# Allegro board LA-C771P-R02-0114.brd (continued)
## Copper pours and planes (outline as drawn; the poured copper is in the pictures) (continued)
BOOT1 on BOTTOM (solid shape): 153.17,63.64 154.22,63.64 154.3,63.57 154.3,63.39 154.23,63.33 152.5,63.33 151.84,63.99 150.8,63.99 150.68,64.11 150.68,64.73 150.78,64.83 151.98,64.83
BOOTG on BOTTOM (solid shape): 160.15,65.01 160.25,65.01 160.33,64.93 160.33,64.02 160.23,63.92 159.9,63.92 159.84,63.86 158.93,62.95 157.48,62.95 157.42,63.01 157.42,63.14 157.48,63.2 158.32,63.2 158.33,63.2 159.26,64.13 159.26,64.67 159.67,65.09 160.08,65.09
BQ24780VDD on BOTTOM (solid shape): 198.78,70.65 198.78,70.52 198.72,70.47 197.91,70.47 197.86,70.42 197.71,70.42 197.4,70.11 197.12,70.11 197.02,70.21 197.02,70.52 197.11,70.61 197.14,70.6 197.27,70.6 197.39,70.65 197.81,70.65 197.84,70.65 197.89,70.7 198.72,70.7
BST_3V on BOTTOM (solid shape): 189.42,40.57 189.92,40.57 189.92,40.57 190,40.57 190.12,40.45 190.12,39.94 190.07,39.89 189.47,39.89 189.36,40 188.85,40 188.79,40.06 187.94,40.06 187.92,40.09 187.92,40.85 188.02,40.95 189.04,40.95
BST_5V on BOTTOM (solid shape): 48.37,48.92 48.37,48.22 48.31,48.16 48.24,48.16 48.23,48.14 47.53,48.14 47.47,48.08 46.12,48.08 46.05,48.16 46.05,48.72 46.14,48.8 47.05,48.8 47.29,49.05 48.24,49.05
BST_CHG on BOTTOM (solid shape): 196.55,71.08 198.72,71.08 198.78,71.03 198.78,70.93 198.72,70.87 197.86,70.87 197.76,70.77 196.97,70.77 196.5,70.3 195.8,70.3 195.8,71.19 196.44,71.19
BST_DDR on BOTTOM (solid shape): 150.05,32.02 150.05,32.01 150.5,31.57 151.72,31.57 152.53,31.57 152.57,31.53 152.57,31.39 152.53,31.35 151.7,31.35 151.64,31.29 150.41,31.29 150.24,31.12 150.24,30.68 150.18,30.61 149.35,30.61 149.29,30.68 149.29,32.21 149.42,32.33 149.73,32.33
BST_DDR_R on BOTTOM (solid shape): 150.31,29.85 150.31,26.82 150.15,26.66 149.31,26.66 149.2,26.77 149.2,28.34 149.29,28.43 149.29,29.85 149.35,29.92 150.24,29.92
CPU_B+ on TOP (solid shape): 157.23,83.45 157.23,82.93 157.45,82.71 158.79,82.71 159.37,82.12 163.56,82.12 163.58,82.1 163.81,82.1 165.08,80.83 165.08,79.51 166.15,78.44 166.15,75.19 165.51,74.56 162.01,74.56 161.48,74.02 161.48,72.81 161.2,72.53 158.23,72.53 158.13,72.63 158.13,73.3 157.94,73.49 157.12,73.49 157.12,73.48 156.22,73.48 156.06,73.65 156.06,74.36 155.87,74.55 155.36,74.55 155.28,74.63 155.28,75.14 155.37,75.23 158.07,75.23 158.36,75.52 158.36,78.35 158.36,78.4 158.36,78.45 158.36,78.97 158.37,79.04 158.36,79.12 158.36,81.8 158.06,82.1 155.37,82.1 155.25,82.22 155.25,83.44 155.39,83.59 157.09,83.59
CPU_B+ on BOTTOM (solid shape): 165.11,80.65 165.11,75.37 164.35,74.61 162.11,74.61 161.53,74.02 161.53,72.86 161.2,72.53 158.22,72.53 158.15,72.6 158.15,76.64 158.42,76.91 158.42,79.48 158.45,79.51 158.45,81.46 159.01,82.03 163.4,82.03 163.48,82.1 163.66,82.1
DCHG_I on TOP (solid shape): 203.36,73.35 203.36,72.4 203.23,72.27 202.6,72.27 202.34,72.53 202.34,73.48 203.23,73.48
DH_CHG on TOP (solid shape): 194.22,72.22 194.22,71.19 194.09,71.07 193.2,71.07 193.07,71.19 193.07,72.27 193.2,72.4 194.04,72.4
DH_CHG on BOTTOM (solid shape): 197.66,71.54 197.89,71.53 197.94,71.48 198.72,71.48 198.78,71.43 198.78,71.33 198.72,71.28 197.89,71.28 197.81,71.21 197.39,71.21 197.21,71.26 197.04,71.21 196.67,71.21 196.59,71.28 196.59,71.57 196.73,71.71 197.48,71.71
DH_CHG on IN2 (solid shape): 197.65,71.57 197.65,70.94 197.52,70.81 196.12,70.81 195.99,70.68 193.2,70.68 193.07,70.81 193.07,71.57 193.2,71.7 197.52,71.7
DL_CHG on TOP (solid shape): 192.11,66.84 192.11,65.77 191.93,65.59 190.96,65.59 190.84,65.72 190.84,66.76 191.09,67.01 191.93,67.01
DL_CHG on BOTTOM (solid shape): 198.78,70.24 198.78,70.11 198.72,70.06 197.94,70.06 197.68,69.81 197.68,69.58 197.56,69.45 196.63,69.45 196.46,69.62 196.46,69.88 196.57,69.99 197.48,69.99 197.78,70.29 198.72,70.29
DL_CHG on IN2 (solid shape): 194.04,66.46 194.04,65.95 193.63,65.54 191.52,65.54 191.35,65.72 191.35,66.63 191.55,66.84 193.66,66.84
DL_CHG on IN2 (solid shape): 197.52,69.86 197.52,69.44 197.43,69.35 197.12,69.35 196.49,68.72 195.8,68.72 195.74,68.78 195.74,69.36 196.36,69.99 197.39,69.99
ECAGND on TOP (solid shape): 68.74,10.4 68.74,7.22 68.18,6.66 67.43,6.66 67.16,6.94 67.13,6.96 67.07,7.01 67,7.05 66.93,7.08 66.86,7.1 66.86,7.34 66.89,7.37 66.89,8.26 66.89,8.29 66.89,8.34 66.88,8.37 66.88,8.54 67.62,8.54 67.62,8.49 67.63,8.44 67.65,8.39 67.67,8.34 67.7,8.3 67.74,8.26 67.78,8.22 67.82,8.2 67.87,8.18 67.92,8.17 67.98,8.16 68.03,8.17 68.08,8.18 68.13,8.2 68.18,8.22 68.22,8.26 68.26,8.3 68.29,8.34 68.31,8.39 68.33,8.44 68.33,8.49 68.33,8.54 68.33,8.6 68.31,8.65 68.29,8.7 68.26,8.74 68.22,8.78 68.18,8.81 68.13,8.84 68.08,8.86 68.03,8.87 67.98,8.87 67.92,8.87 67.87,8.86 67.82,8.84 67.78,8.81 67.74,8.78 67.7,8.74 67.67,8.7 67.65,8.65 67.63,8.6 67.62,8.54 66.88,8.54 66.88,9.15 66.88,9.19 66.87,9.27 66.86,9.31 66.86,9.38 66.88,9.4 66.91,9.42 66.97,9.46 66.99,9.48 67.36,9.85 67.36,9.9 67.39,9.94 67.39,10.85 67.44,10.91 68.23,10.91
EXT_MIC_RING2 on TOP (solid shape): 20.86,26.68 20.86,26.36 20.8,26.27 20.69,26.29 20.11,26.2 20.4,25.69 20.48,25.62 20.46,25.52 20.23,25.28 19.08,25.28 18.96,25.41 18.96,27.31 19.08,27.44 20.1,27.44
EXT_MIC_SLEEVE on TOP (solid shape): 20.78,25.26 20.94,25.11 20.94,24.9 20.8,24.77 20.78,24.77 20.57,24.74 20.42,24.59 20.25,24.42 20.25,23.71 19.69,23.15 19.03,23.15 18.96,23.22 18.96,24.98 19.13,25.15 20.35,25.15 20.48,25.28 20.78,25.28
HGNDB on TOP (solid shape): 16.52,16.42 16.52,15.88 16.4,15.77 16.4,14.58 16.39,14.56 16.39,13.7 16.21,13.52 14.94,13.52 14.79,13.67 14.79,15.02 15.32,15.55 15.32,16.47 15.5,16.65 16.29,16.65
HGNDB on IN2 (solid shape): outline of 159 points within 1.27,12.72 16.31,18.55
LANGND on TOP (solid shape): 18.32,73.38 18.32,72.73 18.17,72.57 16.75,72.57 16.44,72.88 16.44,73.97 16.61,74.14 17.56,74.14
LANGND on TOP (solid shape): outline of 107 points within 5.72,60.29 20.2,63.56
LANGND on BOTTOM (solid shape): 8.79,78.42 15.12,78.42 15.16,78.38 17.04,78.38 18,77.42 18,73.6 17.69,73.28 16.03,73.28 15.58,73.74 15.58,74.22 12.22,77.58 10.44,77.58 10.38,77.63 10.31,77.67 9.09,77.67 8.97,77.55 6.41,77.55 6.1,77.86 6.1,78.44 6.41,78.75 8.47,78.75
LANGND on IN1 (solid shape): outline of 205 points within 6.15,60.23 18.57,78.82
LG_DDR on TOP (solid shape): 148.46,28.97 148.46,28.04 148.32,27.89 147.43,27.89 147.33,28 147.33,28.91 147.45,29.04 148.39,29.04
LG_DDR on BOTTOM (solid shape): 152.97,30.3 152.97,29.53 152.59,29.15 152.59,28.96 152.5,28.87 152.18,28.87 152.02,29.03 152.02,29.79 152.31,30.07 152.62,30.07 152.7,30.14 152.7,30.27 152.77,30.35 152.92,30.35
LG_DDR on IN2 (solid shape): 152.59,29.85 152.59,28.81 152.26,28.48 152.26,28.25 151.77,27.76 148.15,27.76 147.96,27.95 147.96,27.95 147.89,28.02 147.89,28.86 147.99,28.96 148.37,28.96 148.82,28.52 151.09,28.52 151.94,29.37 151.96,29.37 151.96,29.85 152.08,29.98 152.47,29.98
LGATE1 on TOP (solid shape): 155.92,77.55 155.92,76.74 155.82,76.64 155.54,76.64 155.27,76.91 154.84,76.91 154.78,76.97 154.78,77.77 154.84,77.83 155.65,77.83
LGATE1 on BOTTOM (solid shape): 155.68,65.74 155.68,64.95 155.41,64.68 155.41,63.69 155.36,63.64 155.17,63.64 155.13,63.68 155.13,65.17 155.13,65.81 155.23,65.91 155.51,65.91
LGATE1 on IN2 (solid shape): 155.9,66.28 155.9,65.05 155.57,64.72 155.23,64.72 155.13,64.83 155.13,66.35 155.18,66.4 155.78,66.4
LGATE1 on IN2 (solid shape): 156.34,77.2 156.34,76.67 156.22,76.54 155.86,76.54 155.68,76.72 155.14,76.72 154.76,77.1 154.76,77.61 154.99,77.84 155.71,77.84
LGATEG on TOP (solid shape): 158.23,80.54 158.23,79.52 158.14,79.43 157.22,79.43 157.1,79.56 157.1,79.84 157.36,80.09 157.36,80.51 157.49,80.64 158.13,80.64
LGATEG on BOTTOM (solid shape): 157.66,65.89 157.66,65.31 156.99,64.64 156.99,63.67 156.91,63.59 156.81,63.59 156.73,63.67 156.73,65.23 156.79,65.41 156.73,65.6 156.73,65.78 156.9,65.95 157.59,65.95
LGATEG on IN2 (solid shape): 157.77,66.11 157.77,65.46 157.12,64.81 156.88,64.81 156.74,64.94 156.74,66.29 156.84,66.38 157.5,66.38
LGATEG on IN2 (solid shape): 158.99,80.6 158.99,79.74 158.81,79.57 158.09,79.57 157.95,79.43 157.2,79.43 157.1,79.52 157.1,80.5 157.31,80.71 158.88,80.71
LINE2-L on TOP (solid shape): 22.18,22.34 22.18,22.1 21.85,21.77 21.04,20.96 20.33,20.96 19.72,20.35 19.26,20.35 19.08,20.53 19.08,21.88 19.18,21.98 19.91,21.98 20.17,21.72 20.84,21.72 21.28,22.16 21.28,22.32 21.33,22.38 22.14,22.38
LINE2-MIC on TOP (solid shape): 18.93,21.09 18.93,19.9 18.75,19.72 17.76,19.72 17.58,19.9 17.58,21.09 17.71,21.22 18.8,21.22
LINE2-MIC on TOP (solid shape): 25.33,19.01 25.33,18.27 25.33,18.26 25.33,17.91 25.18,17.76 24.87,17.76 24.72,17.92 24.6,17.92 24.49,17.98 24.38,18.03 23.73,18.68 23.73,18.83 24.26,19.36 24.98,19.36
LINE2-MIC on BOTTOM (solid shape): 25.56,77.33 25.56,76.03 25.41,75.88 20.56,75.88 20.23,76.21 20.23,77.22 20.63,77.63 25.26,77.63
LINE2-MIC on IN1 (solid shape): 27.24,77.12 27.24,76.11 27.02,75.89 24.71,75.89 24.37,76.23 24.37,77.02 24.68,77.34 27.02,77.34
LINE2-MIC on IN1 (solid shape): outline of 114 points within 17.63,17.59 25.69,22.21
LX_1.05V on TOP (solid shape): 66.35,64.7 66.35,63.51 66.07,63.23 63.84,63.23 63.51,62.9 63.51,62.11 63.33,61.93 62.41,61.93 62.31,62.03 62.31,62.44 62.24,62.51 61.83,62.51 61.58,62.26 61.58,61.53 61.49,61.45 61.35,61.45 61.27,61.52 61.27,64.62 61.65,65.01 66.05,65.01
LX_3V on BOTTOM (solid shape): 187.92,39.81 188.55,39.81 188.72,39.63 188.72,38.79 188.54,38.61 187.92,38.61 187.76,38.46 187.51,38.46 187.43,38.54 187.43,39.91 187.56,40.04 187.69,40.04
LX_3V on BOTTOM (solid shape): 196.98,39.68 196.98,36.25 198.18,35.06 198.18,32.09 198.02,31.93 196.4,31.93 196.04,32.29 196.04,34.22 194.33,35.94 194.18,35.94 193.3,36.83 193.3,37.51 192.76,38.04 191.71,38.04 191.71,39.21 193.12,39.21 193.43,39.53 193.43,40.45 193.71,40.73 195.94,40.73
LX_3V on IN2 (solid shape): 193.93,39.11 193.93,38.67 193.68,38.41 192.22,38.41 192.09,38.54 192.09,38.92 192.34,39.18 193.87,39.18
LX_3V on IN2 (solid shape): 188.54,39.18 189.05,39.18 189.17,39.06 189.17,38.54 189.1,38.48 187.77,38.48 187.76,38.49 187.43,38.49 187.23,38.69 187.23,39.71 187.52,40 187.72,40
LX_5V on BOTTOM (solid shape): 48.52,51.06 48.52,50.3 48.5,50.28 48.5,49.55 48.37,49.43 47.48,49.43 47.36,49.55 47.36,51.01 47.48,51.14 48.45,51.14
LX_5V on BOTTOM (solid shape): 45.36,45.07 45.64,44.8 46.17,44.8 46.51,44.46 46.51,41.99 46.08,41.55 43.08,41.55 41.33,39.81 40.98,39.81 40.97,39.81 39.02,39.81 38.79,40.04 38.79,41.92 39,42.12 40.94,42.12 41.77,42.95 41.77,44.16 42.47,44.85 43.69,44.85 44.19,45.36 44.19,46.51 45.36,46.51
LX_5V on IN2 (solid shape): 45.25,46.34 45.25,44.76 45.19,44.71 45.19,44.28 45.13,44.22 44.69,44.22 44.5,44.41 44.5,46.25 44.63,46.38 45.2,46.38
LX_5V on IN2 (solid shape): 48.55,50.98 48.55,50.32 47.59,49.36 46.85,49.36 46.85,49.68 47.36,50.19 47.36,50.99 47.45,51.08 48.44,51.08
LX_CHG on TOP (solid shape): 192.88,72.02 192.88,70.81 193.07,70.62 194.72,70.62 194.72,69.4 194.23,68.91 193.53,68.91 193.52,68.9 193.45,68.9 192.76,68.21 192.76,67.57 192.44,67.26 188.95,67.26 188.88,67.32 188.88,69.67 189.07,69.86 190.85,69.86 191.23,70.24 191.23,72.08 191.36,72.21 192.69,72.21
LX_CHG on BOTTOM (solid shape): 192.88,71.45 192.88,68.02 192.57,67.7 187.8,67.7 187.55,67.95 187.55,71.13 188.06,71.64 192.69,71.64
LX_CHG on BOTTOM (solid shape): 197.94,71.89 198.72,71.89 198.78,71.84 198.78,71.71 198.72,71.66 197.75,71.66 197.57,71.84 196.58,71.84 196.44,71.7 196.44,71.51 195.8,71.51 195.8,72.4 197.43,72.4
LX_CHG on IN2 (solid shape): 196.5,72.72 197.52,72.72 197.65,72.59 197.65,71.95 197.58,71.89 193.07,71.89 192.88,71.7 192.88,70.56 192.76,70.43 192.12,70.43 191.93,70.62 191.93,72.4 192.44,72.91 196.31,72.91
LX_DDR on TOP (solid shape): 150.24,32.46 150.24,30.61 149.93,30.3 149.23,30.3 149.04,30.11 149.04,29.41 148.91,29.28 147.96,29.28 147.73,29.51 145.07,29.51 144.64,29.08 143.7,29.08 143.58,29.2 143.58,30.69 143.69,30.8 144.53,30.8 144.97,31.25 144.97,32.2 144.72,32.46 144.72,32.84 145.04,33.15 149.54,33.15
LX_DDR on BOTTOM (solid shape): 149.1,32.55 149.1,29.34 148.97,29.22 147.64,29.22 147.45,29.03 147.45,28.52 147.32,28.39 143.83,28.39 143.64,28.58 143.64,30.8 143.83,31 144.65,31 144.97,31.31 144.97,32.39 144.72,32.65 144.72,32.96 144.97,33.22 148.43,33.22
LX_DDR on BOTTOM (solid shape): 152.57,30.72 152.57,30.54 152.45,30.42 152.02,30.42 151.45,29.85 151.45,27.82 151.39,27.76 150.69,27.76 150.62,27.82 150.62,29.79 150.37,30.04 150.37,30.36 150.5,30.49 151.44,30.49 151.7,30.75 152.53,30.75
LX_DDR on IN2 (solid shape): 151.51,30.34 151.51,30.04 151.39,29.92 147.96,29.92 147.83,30.04 147.83,30.42 147.96,30.55 151.3,30.55
Net_3 on BOTTOM (solid shape): 84.22,50.37 76.22,50.37 76.22,58.37 84.22,58.37
P3 on BOTTOM (solid shape): 44.15,84.69 46.34,84.69 46.44,84.59 46.44,82.15 46.39,82.1 42.55,82.1 42.48,82.18 42.48,83.73 42.3,83.91 41.77,83.91 41.69,83.83 41.69,82.2 41.61,82.13 41,82.13 40.88,82.25 40.88,84.95 41.08,85.15 43.7,85.15
PHASE1 on TOP (solid shape): 151.06,76.62 151.18,76.6 151.3,76.62 151.31,76.62 151.74,76.62 151.75,76.62 151.87,76.6 151.99,76.62 152,76.62 152.44,76.62 152.54,76.6 152.65,76.62 155.36,76.62 155.49,76.48 157.96,76.48 158.02,76.42 158.02,75.43 157.96,75.37 155.43,75.37 155,75.8 154.89,75.8 154.89,75.83 153.74,75.83 153.74,75.8 153.63,75.8 153.54,75.71 153.54,74.36 153.19,74.02 148.61,74.02 148.45,74.17 148.45,76.14 148.45,76.14 148.45,76.37 148.7,76.62 151.05,76.62
PHASE1 on BOTTOM (solid shape): 154.12,66 154.12,66 155,65.12 155,63.66 154.95,63.61 154.79,63.61 154.7,63.69 154.7,64.54 153.98,65.26 153.01,65.26 152.87,65.4 152.87,66.13 152.94,66.2 153.92,66.2
PHASE1 on BOTTOM (solid shape): outline of 95 points within 148.84,70.22 157.73,76.51
PHASE1 on IN2 (solid shape): 154.8,65.84 154.8,64.95 154.72,64.87 154.28,64.87 153.33,65.82 153.33,66.54 153.43,66.65 153.99,66.65
PHASE1 on IN2 (solid shape): 155.73,76.13 155.73,75.59 155.58,75.43 154.01,75.43 153.87,75.56 153.87,76.23 154.03,76.39 155.48,76.39
PHASEG on TOP (solid shape): 151.52,84.06 154.94,84.06 155.08,83.93 155.08,82.18 155.34,81.92 157.9,81.92 158,81.82 158,80.87 157.9,80.77 154.77,80.77 154.6,80.94 151.43,80.94 151.3,81.07 151.25,81.14 151.18,81.19 149.94,82.43 148.88,82.43 148.51,82.8 148.51,83.91 148.8,84.2 151.39,84.2
PHASEG on BOTTOM (solid shape): 158.83,66.17 158.83,65.44 158.86,65.44 158.86,65.21 157.27,63.62 157.17,63.62 157.11,63.67 157.11,64.49 157.97,65.34 157.97,66.15 158.05,66.23 158.77,66.23
PHASEG on BOTTOM (solid shape): 157.99,84.36 157.99,81.09 157.64,80.74 154.74,80.74 154.56,80.56 154.56,79.64 154.47,79.54 154.28,79.54 154.2,79.46 154.2,78.9 154.19,78.83 154.19,78.76 154.19,78.73 154.1,78.64 152.7,78.64 152.69,78.65 152.53,78.68 152.37,78.65 152.36,78.64 152.01,78.64 152,78.64 151.85,78.67 151.71,78.64 151.7,78.64 151.66,78.64 151.53,78.77 151.53,79.99 151.62,80.08 154.28,80.08 154.29,80.1 154.29,80.86 154.28,80.87 151.26,80.87 150.9,81.23 150.9,84.13 151.23,84.46 151.57,84.46 151.95,84.08 152.33,84.46 155.1,84.46 155.32,84.69 157.66,84.69
PHASEG on IN2 (solid shape): 156.4,82.16 156.4,81.57 156.12,81.29 155.42,81.29 155.19,81.06 154.87,81.06 154.59,81.34 154.59,82.1 154.75,82.27 156.3,82.27
PHASEG on IN2 (solid shape): 159.14,65.9 159.14,65.47 159.05,65.38 159.04,65.38 158.92,65.26 158.92,65.25 158.11,64.45 157.79,64.45 157.63,64.61 157.63,65.13 158.45,65.94 159.09,65.94
SPK_L1- on BOTTOM (solid shape): 30.97,26.24 30.97,26.01 30.41,25.46 30.38,25.46 29.9,24.97 28.62,24.97 28.58,25.01 28.58,25.43 29.62,26.47 30.74,26.47
SPK_L1-_CONN on BOTTOM (solid shape): 186.17,94.17 186.17,92.36 186.11,92.3 186.11,88.68 185.84,88.4 185.48,88.12 185.34,87.69 185.34,86.57 185.36,86.41 185.4,86.27 185.4,85.6 185.74,85.26 185.74,83.89 185.55,83.7 184.63,83.7 184.05,84.28 184.05,88.6 184.08,88.63 184.09,88.63 184.72,89.14 184.77,89.95 184.77,89.96 184.77,90.18 185.07,90.49 185.07,91.64 185.12,91.69 185.12,93.98 185.42,94.29 186.06,94.29
SPK_L2+ on BOTTOM (solid shape): 31.4,24.77 31.4,24.24 30.92,23.76 29.52,23.76 29.47,23.76 29.43,23.76 28.61,23.76 28.45,23.91 28.45,24.52 28.66,24.72 30,24.72 30.49,25.2 30.97,25.2
SPK_L2+_CONN on BOTTOM (solid shape): 187.79,93.95 187.79,91.77 188.01,91.54 188.01,90.46 188.1,90.37 188.06,90.33 187.95,90.2 187.86,90.05 187.85,90.04 187.81,90 187.81,89.94 187.81,89.94 187.76,89.61 187.81,89.28 187.81,89.27 187.81,88.83 188.52,88.12 188.52,85.88 187.83,85.19 187.83,84.13 187.33,83.63 186.74,83.63 186.37,84 186.37,85.5 186.98,86.11 186.98,87.69 186.86,87.81 186.85,87.82 186.78,88.04 186.63,88.23 186.62,88.25 186.62,88.46 186.62,88.47 186.62,92.09 186.68,92.15 186.68,94.15 186.74,94.21 187.53,94.21
UG_DDR on TOP (solid shape): 144.72,32.07 144.72,31.3 144.48,31.06 143.7,31.06 143.58,31.19 143.58,32.07 143.7,32.2 144.59,32.2
UG_DDR on BOTTOM (solid shape): 152.57,31.11 152.57,31 152.52,30.94 151.7,30.94 151.39,30.63 150.47,30.63 150.37,30.73 150.37,31.03 150.5,31.16 150.86,31.16 150.87,31.15 150.99,31.13 151.11,31.15 151.12,31.16 151.69,31.16 152.52,31.16
UG_DDR on IN2 (solid shape): 151.54,31.25 151.54,30.8 151.42,30.68 149.45,30.68 149.45,31.31 149.58,31.44 151.35,31.44
UG_DDR on IN2 (solid shape): 144.94,32.11 144.94,31.91 145.07,31.78 145.55,31.78 145.62,31.7 145.62,31.04 145.52,30.94 143.74,30.94 143.41,31.27 143.41,32.19 143.57,32.34 144.71,32.34
UGATE1 on TOP (solid shape): 155.91,74.32 155.91,73.4 155.8,73.29 153.91,73.29 153.83,73.37 153.83,74.02 153.84,74.03 153.84,74.31 153.88,74.35 154.82,74.35 155.2,74.35 155.27,74.42 155.81,74.42
UGATE1-1 on TOP (solid shape): 154.76,75.67 154.82,75.67 154.89,75.6 154.89,74.6 154.77,74.48 153.91,74.48 153.73,74.66 153.73,75.67 153.87,75.67 153.87,75.71 154.76,75.71
UGATE1-1 on BOTTOM (solid shape): 153.06,64.71 154.35,64.71 154.57,64.49 154.57,63.66 154.54,63.62 154.43,63.62 154.09,63.96 153.07,63.96 153,64.03 152.46,64.58 152.46,64.88 152.59,65.01 152.76,65.01
UGATE1-1 on IN2 (solid shape): 153.29,65.12 153.74,65.12 154.23,64.64 154.23,64.3 153.97,64.05 152.5,64.05 152,64.54 152,65.13 152.15,65.29 153.12,65.29
UGATE1-1 on IN2 (solid shape): 155.1,74.94 155.1,74.56 155.05,74.51 155.05,73.49 154.97,73.41 153.83,73.41 153.73,73.51 153.73,74.33 153.71,74.35 153.71,74.87 153.85,75.01 155.03,75.01
UGATEG1 on TOP (solid shape): 159.85,83.8 159.85,82.64 159.75,82.53 159.27,82.53 158.96,82.84 157.54,82.84 157.36,83.02 157.36,83.99 157.49,84.12 159.53,84.12
UGATEG1-1 on TOP (solid shape): 162.54,83.5 162.54,82.66 162.13,82.25 161.16,82.25 160.94,82.47 160.33,82.47 160.22,82.58 160.22,83.52 160.32,83.62 162.42,83.62
UGATEG1-1 on BOTTOM (solid shape): 159.11,64.39 159.11,64.18 158.27,63.33 157.48,63.33 157.42,63.39 157.42,63.56 158.59,64.72 158.78,64.72
UGATEG1-1 on IN2 (solid shape): 160.14,65.36 160.14,65.04 158.74,63.65 158,63.65 157.85,63.79 157.85,64 159.27,65.43 160.08,65.43
UGATEG1-1 on IN2 (solid shape): 162.92,82.44 162.92,81.77 162.62,81.47 161.54,81.47 160.84,82.17 160.84,83.19 161.22,83.57 161.79,83.57
VGA_V1P35_S3_F1 on BOTTOM (solid shape): 125.33,93.17 125.33,92.21 125,91.88 120.58,91.88 119.13,90.43 119.13,90.14 118.99,90 118.83,90 118.73,90.1 118.73,90.45 118.78,90.51 118.78,90.91 119.29,91.43 119.29,91.45 119.31,91.48 119.31,91.51 119.34,91.58 119.42,91.61 119.78,91.97 119.42,92.32 119.34,92.35 119.31,92.42 119.31,92.57 119.16,92.72 119.11,92.81 119.06,92.87 119.06,93.25 119.06,93.25 119.06,93.66 119.43,94.03 119.48,94.04 119.51,93.99 119.51,93.99 120.07,93.99 120.07,94.07 124.44,94.07
VL on BOTTOM (solid shape): 45.53,51.34 45.53,49.64 45.82,49.35 45.82,47.57 45.57,47.57 45.57,48.69 44.88,49.38 44.88,51.33 45.02,51.47 45.4,51.47
VMB on BOTTOM (solid shape): 210.09,87.13 210.09,83.58 208.28,81.77 205.93,81.77 205.8,81.9 205.8,82.79 205.67,82.91 204.93,82.91 204.38,83.47 204.38,86.27 204.2,86.45 204.2,87.89 204.38,88.07 209.15,88.07
VMB2 on BOTTOM (solid shape): 206.56,93.15 206.56,89.06 206.33,88.83 204.2,88.83 204,89.04 204,90.79 203.21,91.58 202.36,91.58 202.14,91.8 202.14,93.35 202.39,93.6 206.1,93.6
VMB2 on BOTTOM (solid shape): 208.73,92.83 208.73,89.36 208.2,88.83 204.63,88.83 204.32,89.13 204.32,90.46 203.21,91.58 202.36,91.58 202.14,91.8 202.14,93.35 202.39,93.6 207.96,93.6
N10380 on BOTTOM (solid shape): 39.2,90.33 39.2,87.23 39.08,87.11 39.02,87.11 38.96,87.05 38.29,87.05 37.57,87.77 37.57,89.8 38.21,90.43 39.1,90.43
N16597291 on BOTTOM (solid shape): 187.25,38.79 186.61,38.79 186.61,39.78 186.61,39.78 186.61,40.95 187.25,40.95
N16598283 on BOTTOM (solid shape): 49.77,50.19 49.77,48.28 49.64,48.16 49.01,48.16 48.94,48.22 48.94,50.25 49.01,50.32 49.64,50.32
N16600766 on BOTTOM (solid shape): 154.18,30.3 154.18,29.41 154.38,29.2 154.38,28.37 154.23,28.21 153.93,28.21 153.88,28.26 153.88,28.53 153.92,28.57 153.92,28.67 153.93,28.67 153.93,29.36 153.98,29.41 153.98,30.3 154.03,30.35 154.13,30.35
N16602606 on TOP (solid shape): 61.6,60.05 61.6,59.01 61.68,58.93 62.42,58.93 62.95,59.47 64.94,59.47 65.04,59.37 65.04,57.81 64.46,57.23 61.47,57.23 61.19,57.51 61.19,58.96 61.28,59.05 61.28,60.03 61.34,60.09 61.56,60.09
N16602704 on TOP (solid shape): 65.52,62.94 65.72,62.94 65.89,62.77 65.89,61.47 65.42,60.99 63.66,60.99 63.58,61.07 63.58,61.81 63.84,62.06 63.84,62.7 64.09,62.95 65.51,62.95
N16605295 on TOP (solid shape): 71.59,79.44 71.59,77.28 71.53,77.22 71.08,77.22 71.02,77.15 71.02,76.71 71.08,76.65 71.53,76.65 71.59,76.58 71.59,76.46 71.53,76.39 71.08,76.39 71.02,76.33 71.02,75.88 71.08,75.82 71.53,75.82 71.59,75.76 71.59,75.31 71.34,75.06 65.75,75.06 65.62,75.19 65.62,77.04 68.52,77.04 68.52,76.98 68.53,76.93 68.55,76.88 68.57,76.83 68.6,76.79 68.64,76.75 68.68,76.71 68.72,76.69 68.77,76.67 68.83,76.66 68.88,76.65 68.93,76.66 68.98,76.67 69.03,76.69 69.08,76.71 69.12,76.75 69.16,76.79 69.19,76.83 69.21,76.88 69.23,76.93 69.24,76.98 69.24,77.04 69.23,77.09 69.21,77.14 69.19,77.19 69.16,77.23 69.12,77.27 69.08,77.3 69.03,77.33 68.98,77.35 68.93,77.36 68.88,77.37 68.83,77.36 68.77,77.35 68.72,77.33 68.68,77.3 68.64,77.27 68.6,77.23 68.57,77.19 68.55,77.14 68.53,77.09 68.52,77.04 65.62,77.04 65.62,77.41 65.75,77.54 68.29,77.54 68.6,77.85 68.6,79.63 68.8,79.82 71.21,79.82
N16616404 on BOTTOM (solid shape): 161.75,65.47 161.75,64.15 161.6,63.99 161.01,63.99 160.71,64.3 160.71,64.93 160.51,65.14 160.2,65.14 159.85,65.49 159.06,65.49 158.99,65.57 158.99,66.21 159.1,66.32 160.9,66.32
N16616872 on BOTTOM (solid shape): 152.62,66.19 152.62,65.5 152.51,65.39 150.85,65.39 150.74,65.5 150.74,66.16 150.83,66.25 152.57,66.25
N16617930 on TOP (solid shape): 149.31,79.23 149.31,78.49 149.38,78.41 150.25,78.41 150.32,78.34 150.32,77.14 150.25,77.07 148.39,77.07 148.09,77.37 148.09,79.23 148.22,79.35 149.18,79.35
N16618186 on TOP (solid shape): 150.58,81.41 150.58,80.7 150.32,80.45 149.43,80.45 149.31,80.32 149.31,79.66 149.13,79.48 148.32,79.48 147.99,79.81 147.99,81.41 148.37,81.79 150.2,81.79
N18492193 on BOTTOM (solid shape): 118.83,60.77 118.83,56.57 118.76,56.5 117.77,56.5 117.64,56.63 117.64,59.78 117.99,60.13 117.99,60.76 118.1,60.87 118.73,60.87
N18492196 on BOTTOM (solid shape): 115.91,59.44 116.59,59.44 116.67,59.37 116.67,56.75 116.49,56.57 114.84,56.57 114.64,56.78 114.64,59.7 114.69,59.75 115.6,59.75
N18535411 on TOP (solid shape): 18.7,71.89 18.7,69.98 18.57,69.86 17.43,69.86 17.18,70.11 17.18,71.89 17.43,72.14 18.45,72.14
N18535413 on TOP (solid shape): 20.23,69.35 20.23,64.37 19.9,64.04 16.59,64.04 16.19,64.44 16.19,68.46 16.24,68.55 16.35,68.55 16.89,68.75 16.52,69.2 16.42,69.26 16.44,69.37 16.57,69.5 16.59,69.51 16.73,69.56 16.84,69.67 19.91,69.67
N24385422 on BOTTOM (solid shape): 195.28,72.27 195.28,70.29 195.13,70.14 194.57,70.14 194.37,70.34 194.37,71.14 194.37,71.15 194.39,71.28 194.37,71.41 194.37,71.42 194.37,72.35 194.5,72.48 195.08,72.48
N24385504 on BOTTOM (solid shape): 47.47,88.72 47.47,87.69 47.52,87.64 47.52,87.62 48.31,86.83 48.31,86.15 48.24,86.09 46.87,86.09 46.57,86.39 45.96,86.39 45.8,86.24 45.8,85.1 45.68,84.97 44.08,84.97 43.62,85.43 43.62,85.45 43.44,85.63 43.44,86.98 44,87.54 44,88.6 44.31,88.91 47.28,88.91
N24385542 on TOP (solid shape): 190.66,72.97 190.66,70.56 190.53,70.43 188.82,70.43 188.37,69.99 188.37,68.14 187.49,67.26 184.44,67.26 184.37,67.32 184.37,68.4 184.82,68.84 185.96,68.84 186.41,69.29 186.41,72.97 186.66,73.22 190.41,73.22
N24385542 on BOTTOM (solid shape): 186.72,68.46 186.72,67.26 184.44,67.26 184.37,67.32 184.37,68.53 184.56,68.72 186.47,68.72
N24385612 on BOTTOM (solid shape): 198.79,72.27 198.79,72.14 198.71,72.07 197.94,72.07 197.93,72.08 197.88,72.14 197.88,72.17 197.26,72.78 194.72,72.78 194.72,73.8 197.26,73.8
N24385720 on TOP (solid shape): 190.58,80.43 190.58,79.16 191.09,78.65 191.09,78.01 190.89,77.81 188.91,77.81 187.94,78.77 187.94,80.2 188.53,80.78 190.23,80.78
N24386383 on BOTTOM (solid shape): 42.04,87.77 42.04,86.04 41.54,85.53 40.93,85.53 39.83,84.44 39.28,84.44 39.02,84.69 39.02,86.21 39.28,86.48 39.46,86.48 39.56,86.57 40.25,86.57 40.83,87.14 40.83,87.72 40.98,87.87 41.94,87.87
N24386941 on TOP (solid shape): 194.03,73.1 193.9,72.97 192.95,72.97 192.44,72.46 191.42,72.46 191.3,72.59 191.3,72.97 191.49,73.16 191.93,73.16 192.5,73.73 194.03,73.73
N24595306 on BOTTOM (solid shape): 43.8,88.63 43.8,87.56 43.26,87.03 43.26,85.71 43.11,85.56 42.37,85.56 42.35,85.58 42.35,88.12 43.06,88.83 43.59,88.83
N28204186 on TOP (solid shape): 195.87,67.95 195.87,66.18 195.23,65.54 194.19,65.54 193.96,65.77 193.96,66.43 193.58,66.81 193.07,66.81 192.95,66.94 192.95,67.95 193.2,68.21 195.61,68.21

Small or netless copper shapes (teardrops, artwork), in the pictures only: 15 on TOP, 23 on BOTTOM

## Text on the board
Ref Des/Silkscreen Bottom: M2X3
User.Comments: LA-C771P | 2016-01-14 | 2015-01-14 | Minjia_Cai | AIVP1/AIVP2 | 0.2
User.37: 5 / 5.5
User.38: FIGURE | SIZE | 8.0 | 22.0 | 24.0 | 28.0 | 35.0 | 43.0 | 118.0 | 150.0 | 31.0 | 47.0 | 63.0 | 67.0 | 71.0 | 35.0x16.0 | 36.0x18.0 | 49.0x26.0 | 55.0x28.0 | 63.0x35.0 | 67.0x24.0 | 71.0x28.0 | 79.0x31.0 | 93.0x28.0 | 94.0x28.0 | 94.0x39.0 | 142.0x122.0 | DRILL CHART: TOP to BOTTOM | ALL UNITS ARE IN MILS | TOLERANCE | +3.0/-3.0 | +2.0/-2.0 | PLATED | NON-PLATED | QTY | 2964 | 19 | 8 | 38 | 12 | 7 | 9 | 4 | 1 | 2 | 3 | 26
